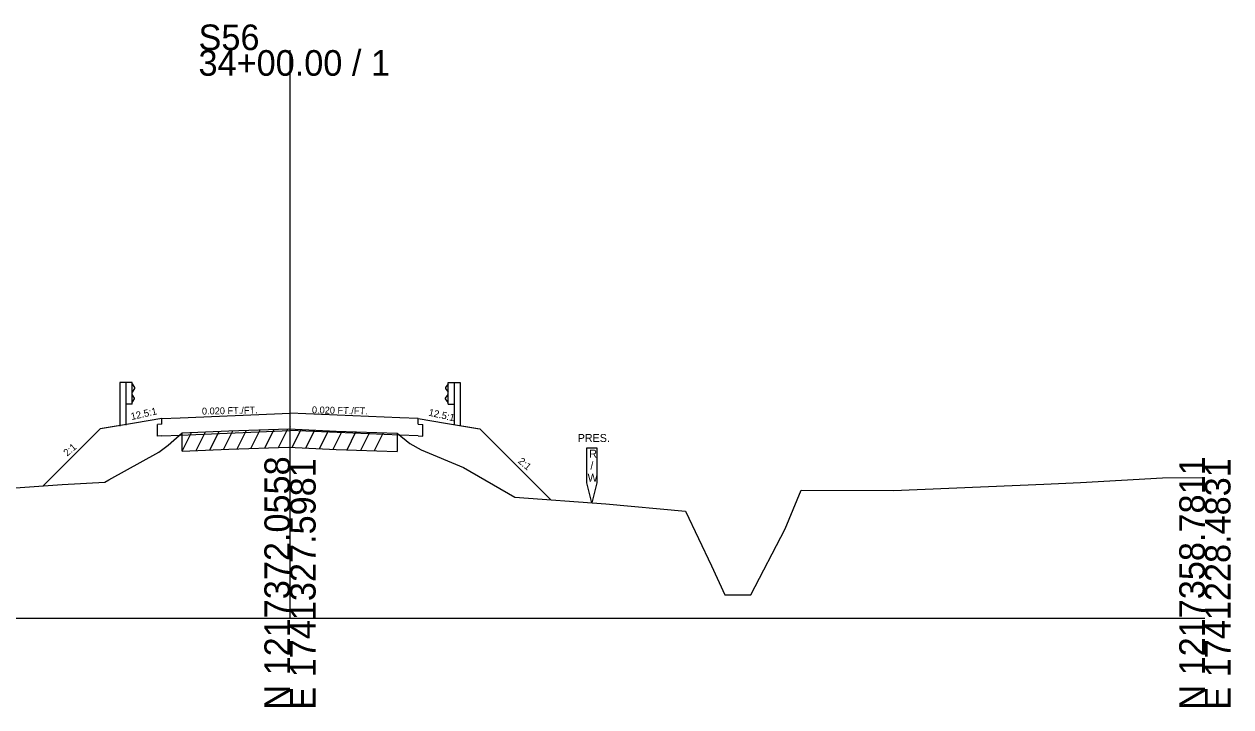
# Model space of a CAD drawing. Extents: x -26 to 1203, y -10 to 19541.
# Drawn here: x 70.9 to 202.8, y 8990.3 to 9064.9 of the extents above; entities that cross this region are included whole.
import ezdxf

# ---------------------------------------------------------------- set-up
doc = ezdxf.new("R2010")
doc.units = 0
for name, color, linetype in [('RD_GPK_XS_Cell', 7, 'Continuous'), ('RD_XS_Base', 7, 'Continuous'), ('RD_XS_EarthShd', 7, 'Continuous'), ('RD_XS_ExGround', 7, 'Continuous'), ('RD_XS_ExPaveRet', 7, 'Continuous'), ('RD_XS_ExRW', 7, 'Continuous'), ('RD_XS_GR', 7, 'Continuous'), ('RD_XS_Pave', 7, 'Continuous'), ('RD_XS_TX_Elev_EX', 7, 'Continuous'), ('RD_XS_TX_Slope', 7, 'Continuous')]:
    doc.layers.add(name, color=color, linetype=linetype)

msp = doc.modelspace()

# ---------------------------------------------------------------- linework, layer by layer
at = {"layer": 'RD_GPK_XS_Cell'}
for p, q in [((100, 9000), (100, 9062.09)), ((0, 9000), (100, 9000)), ((100, 9000), (200, 9000))]:
    msp.add_line(p, q, dxfattribs=at)
at = {"layer": 'RD_XS_Base'}
for p, q in [((86, 9021.19), (85.5, 9021.17)), ((85.5, 9019.9), (85.5, 9021.17)), ((86, 9021.19), (86, 9021.83)), ((114, 9021.19), (114, 9021.83)), ((114, 9021.19), (114.5, 9021.17)), ((114.5, 9019.9), (114.5, 9021.17)), ((86, 9019.92), (85.5, 9019.9)), ((86, 9019.92), (88, 9020.01)), ((88, 9020.01), (100, 9020.51)), ((112, 9020.01), (100, 9020.51)), ((114, 9019.92), (112, 9020.01)), ((114, 9019.92), (114.5, 9019.9))]:
    msp.add_line(p, q, dxfattribs=at)
at = {"layer": 'RD_XS_EarthShd'}
for p, q in [((83, 9021.33), (79.25, 9020.7)), ((83, 9021.33), (79.5, 9020.75)), ((86, 9021.83), (83, 9021.33)), ((114, 9021.83), (117, 9021.33)), ((117, 9021.33), (120.5, 9020.75)), ((117, 9021.33), (120.75, 9020.7)), ((73.02, 9014.47), (79.25, 9020.7)), ((128.51, 9012.94), (120.75, 9020.7))]:
    msp.add_line(p, q, dxfattribs=at)
at = {"layer": 'RD_XS_ExGround'}
msp.add_lwpolyline([(44.95, 9012.47), (75.08, 9014.62), (79.75, 9014.88), (80.18, 9015.11), (85.67, 9018.16), (86.68, 9018.92), (88.23, 9020.25), (93.32, 9020.48), (99.84, 9020.7), (105.04, 9020.45), (111.71, 9020.23), (113.1, 9019.08), (114.32, 9018.41), (118.98, 9016.48), (124.58, 9013.23), (134.51, 9012.51), (143.23, 9011.7), (146.07, 9005.74), (147.54, 9002.56), (149.41, 9002.55), (150.36, 9002.55), (154.11, 9009.78), (155.86, 9014.01), (165.97, 9013.97), (182.41, 9014.66), (186.4, 9014.82), (195.35, 9015.33), (200, 9015.37)], dxfattribs=at)
at = {"layer": 'RD_XS_ExPaveRet'}
for p, q in [((88.23, 9018.25), (89.25, 9020.3)), ((88.23, 9018.25), (88.23, 9020.25)), ((89.73, 9018.32), (90.75, 9020.36)), ((91.23, 9018.38), (92.25, 9020.43)), ((92.73, 9018.45), (93.75, 9020.49)), ((94.23, 9018.51), (95.25, 9020.54)), ((95.73, 9018.56), (96.75, 9020.59)), ((97.23, 9018.61), (98.25, 9020.64)), ((98.73, 9018.66), (99.75, 9020.69)), ((100.23, 9018.68), (101.21, 9020.63)), ((101.73, 9018.61), (102.71, 9020.56)), ((103.23, 9018.53), (104.21, 9020.49)), ((104.73, 9018.46), (105.71, 9020.43)), ((106.23, 9018.41), (107.21, 9020.38)), ((107.73, 9018.36), (108.71, 9020.33)), ((109.23, 9018.31), (110.21, 9020.28)), ((111.71, 9020.23), (111.71, 9018.23)), ((88.23, 9018.25), (93.32, 9018.48)), ((93.32, 9018.48), (99.84, 9018.7)), ((99.84, 9018.7), (105.04, 9018.45)), ((105.04, 9018.45), (111.71, 9018.23))]:
    msp.add_line(p, q, dxfattribs=at)
at = {"layer": 'RD_XS_ExRW'}
msp.add_lwpolyline([(132.45, 9018.63), (133.55, 9018.63), (133.55, 9014.8), (133, 9012.62), (132.45, 9014.8)], close=True, dxfattribs=at)
at = {"layer": 'RD_XS_GR'}
for p, q in [((81.4, 9025.75), (81.4, 9020.98)), ((82.06, 9025.75), (81.4, 9025.75)), ((82.06, 9025.75), (82.06, 9021.09)), ((82.73, 9025.75), (82.06, 9025.75)), ((82.73, 9023.41), (82.73, 9025.75)), ((82.73, 9025.6), (83, 9025.2)), ((83, 9025.1), (82.73, 9024.7)), ((83, 9025.2), (83, 9025.1)), ((117.27, 9025.6), (117, 9025.2)), ((117, 9025.2), (117, 9025.1)), ((117, 9025.1), (117.27, 9024.7)), ((117.27, 9023.41), (117.27, 9025.75)), ((117.27, 9025.75), (117.94, 9025.75)), ((117.94, 9025.75), (117.94, 9021.09)), ((117.94, 9025.75), (118.6, 9025.75)), ((118.6, 9025.75), (118.6, 9020.98)), ((82.73, 9023.41), (82.06, 9023.41)), ((83, 9024.06), (82.73, 9024.46)), ((82.73, 9023.56), (83, 9023.96)), ((83, 9023.96), (83, 9024.06)), ((117, 9024.06), (117.27, 9024.46)), ((117, 9023.96), (117, 9024.06)), ((117.27, 9023.56), (117, 9023.96)), ((117.27, 9023.41), (117.94, 9023.41))]:
    msp.add_line(p, q, dxfattribs=at)
at = {"layer": 'RD_XS_Pave'}
for p, q in [((88, 9021.91), (100, 9022.41)), ((112, 9021.91), (100, 9022.41)), ((86, 9021.83), (88, 9021.91)), ((114, 9021.83), (112, 9021.91))]:
    msp.add_line(p, q, dxfattribs=at)

# ---------------------------------------------------------------- texts
at = {"layer": 'RD_GPK_XS_Cell'}
for s, p in [('S56', (90, 9062.09)), ('34+00.00 / 1', (90, 9059.29))]:
    msp.add_text(s, height=2.8, dxfattribs=at).set_placement(p)
for s, p in [('N 1217372.0558', (100, 8990)), ('E 1741327.5981', (102.8, 8990)), ('N 1217358.7811', (200, 8990)), ('E 1741228.4831', (202.8, 8990))]:
    msp.add_text(s, height=2.8, rotation=90, dxfattribs=at).set_placement(p)
at = {"layer": 'RD_XS_ExRW'}
for s, p in [('PRES.', (131.45, 9019.26)), ('R', (132.71, 9017.54)), ('/', (132.83, 9016.23)), ('W', (132.53, 9014.92))]:
    msp.add_text(s, height=0.875, dxfattribs=at).set_placement(p)
at = {"layer": 'RD_XS_TX_Elev_EX'}
msp.add_text('845.34', height=0.1, rotation=90, dxfattribs=at).set_placement((100.1, 9020.69))
at = {"layer": 'RD_XS_TX_Slope'}
for s, height, rotation, p in [('12.5:1', 0.778, 12.7511, (82.69, 9021.65)), ('0.020 FT./FT.', 0.7518, 1.1916, (90.38, 9022.25)), ('0.020 FT./FT.', 0.7518, 358.8084, (102.39, 9022.4)), ('12.5:1', 0.778, 347.2489, (115.09, 9022.15)), ('2:1', 0.778, 40.6589, (75.64, 9017.65)), ('2:1', 0.778, 319.3411, (124.86, 9017.05))]:
    msp.add_text(s, height=height, rotation=rotation, dxfattribs=at).set_placement(p)

doc.saveas('drawing.dxf')
